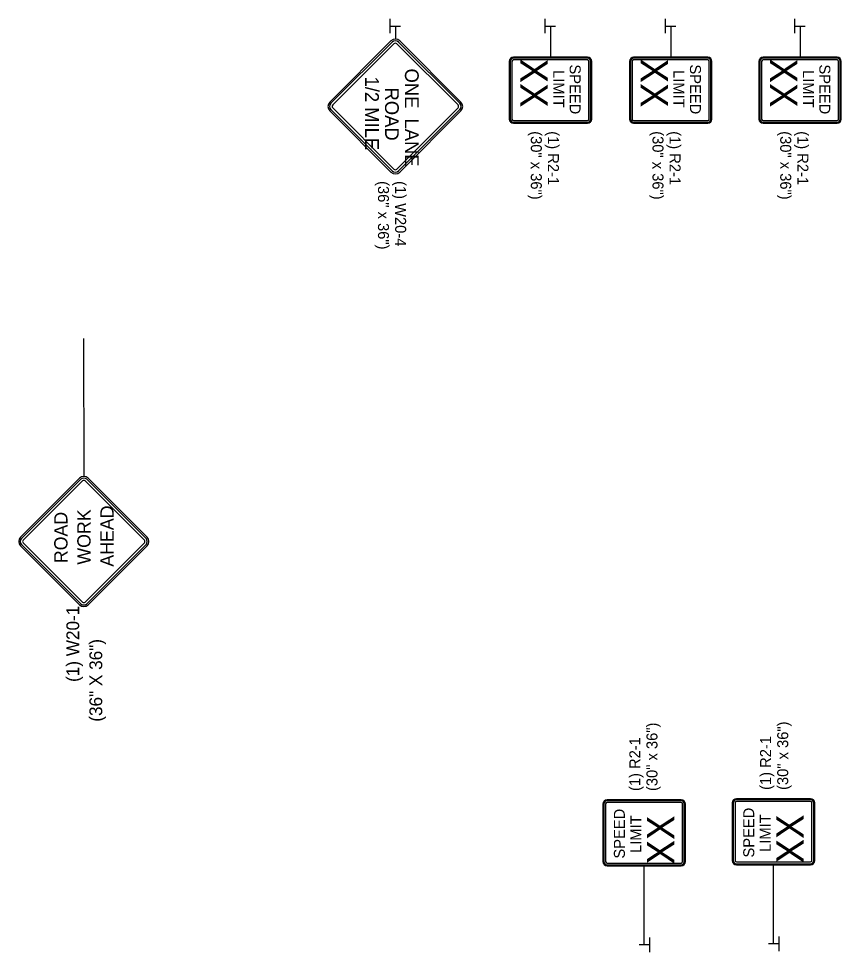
# Model space of a CAD drawing. Extents: x 1925873 to 1930787, y 596452 to 599617.
# Drawn here: x 1926733 to 1927182, y 598960 to 599469 of the extents above; entities that cross this region are included whole.
import ezdxf

# ---------------------------------------------------------------- set-up
doc = ezdxf.new("R2010")
doc.units = 0
for name, color, linetype in [('Default', 7, 'Continuous'), ('P_TC_Signs_Permanent', 7, 'Continuous'), ('P_TC_Signs_Temporary', 7, 'Continuous'), ('R_Border', 7, 'Continuous')]:
    doc.layers.add(name, color=color, linetype=linetype)

msp = doc.modelspace()

# ---------------------------------------------------------------- linework, layer by layer
at = {"layer": 'Default'}
for p, q in [((1926935.77, 599461.2), (1926935.77, 599469.2)), ((1927020.43, 599461.2), (1927020.43, 599469.2)), ((1927086.08, 599461.2), (1927086.08, 599469.2)), ((1927156.69, 599461.2), (1927156.69, 599469.2)), ((1926935.89, 599465.18), (1926941.35, 599465.18)), ((1927020.55, 599465.18), (1927026.01, 599465.18)), ((1927086.2, 599465.18), (1927091.66, 599465.18)), ((1927156.81, 599465.18), (1927162.27, 599465.18)), ((1927077.25, 598967.54), (1927077.25, 598959.53)), ((1927147.86, 598968.12), (1927147.86, 598960.11)), ((1927077.14, 598963.55), (1927071.67, 598963.55)), ((1927147.75, 598964.13), (1927142.28, 598964.13))]:
    msp.add_line(p, q, dxfattribs=at)
at = {"layer": 'P_TC_Signs_Permanent'}
for p, q in [((1927000.78, 599445.9), (1927000.78, 599414.4)), ((1927001.34, 599445.9), (1927001.34, 599414.4)), ((1927002.28, 599445.9), (1927002.28, 599414.4)), ((1927043.53, 599448.15), (1927003.03, 599448.15)), ((1927043.53, 599447.59), (1927003.03, 599447.59)), ((1927043.53, 599446.65), (1927003.03, 599446.65)), ((1927044.28, 599414.4), (1927044.28, 599445.9)), ((1927045.22, 599414.4), (1927045.22, 599445.9)), ((1927045.78, 599414.4), (1927045.78, 599445.9)), ((1927066.43, 599445.9), (1927066.43, 599414.4)), ((1927066.99, 599445.9), (1927066.99, 599414.4)), ((1927067.93, 599445.9), (1927067.93, 599414.4)), ((1927109.18, 599448.15), (1927068.68, 599448.15)), ((1927109.18, 599447.59), (1927068.68, 599447.59)), ((1927109.18, 599446.65), (1927068.68, 599446.65)), ((1927109.93, 599414.4), (1927109.93, 599445.9)), ((1927110.87, 599414.4), (1927110.87, 599445.9)), ((1927111.43, 599414.4), (1927111.43, 599445.9)), ((1927137.04, 599445.9), (1927137.04, 599414.4)), ((1927137.6, 599445.9), (1927137.6, 599414.4)), ((1927138.54, 599445.9), (1927138.54, 599414.4)), ((1927179.79, 599448.15), (1927139.29, 599448.15)), ((1927179.79, 599447.59), (1927139.29, 599447.59)), ((1927179.79, 599446.65), (1927139.29, 599446.65)), ((1927180.54, 599414.4), (1927180.54, 599445.9)), ((1927181.48, 599414.4), (1927181.48, 599445.9)), ((1927182.04, 599414.4), (1927182.04, 599445.9)), ((1927003.03, 599413.65), (1927043.53, 599413.65)), ((1927003.03, 599412.71), (1927043.53, 599412.71)), ((1927003.03, 599412.15), (1927043.53, 599412.15)), ((1927068.68, 599413.65), (1927109.18, 599413.65)), ((1927068.68, 599412.71), (1927109.18, 599412.71)), ((1927068.68, 599412.15), (1927109.18, 599412.15)), ((1927139.29, 599413.65), (1927179.79, 599413.65)), ((1927139.29, 599412.71), (1927179.79, 599412.71)), ((1927139.29, 599412.15), (1927179.79, 599412.15)), ((1927094.65, 599042.78), (1927054.15, 599042.78)), ((1927165.26, 599043.35), (1927124.76, 599043.35)), ((1927165.26, 599042.79), (1927124.76, 599042.79)), ((1927051.9, 599040.53), (1927051.9, 599009.03)), ((1927052.47, 599040.53), (1927052.47, 599009.03)), ((1927053.4, 599040.53), (1927053.4, 599009.03)), ((1927094.65, 599042.21), (1927054.15, 599042.21)), ((1927094.65, 599041.28), (1927054.15, 599041.28)), ((1927095.4, 599009.03), (1927095.4, 599040.53)), ((1927096.34, 599009.03), (1927096.34, 599040.53)), ((1927096.9, 599009.03), (1927096.9, 599040.53)), ((1927122.51, 599041.1), (1927122.51, 599009.6)), ((1927123.08, 599041.1), (1927123.08, 599009.6)), ((1927124.01, 599041.1), (1927124.01, 599009.6)), ((1927165.26, 599041.85), (1927124.76, 599041.85)), ((1927166.01, 599009.6), (1927166.01, 599041.1)), ((1927166.95, 599009.6), (1927166.95, 599041.1)), ((1927167.51, 599009.6), (1927167.51, 599041.1)), ((1927054.15, 599008.28), (1927094.65, 599008.28)), ((1927054.15, 599007.34), (1927094.65, 599007.34)), ((1927124.76, 599008.85), (1927165.26, 599008.85)), ((1927124.76, 599007.92), (1927165.26, 599007.92)), ((1927124.76, 599007.35), (1927165.26, 599007.35)), ((1927054.15, 599006.78), (1927094.65, 599006.78))]:
    msp.add_line(p, q, dxfattribs=at)
for centre, radius, start, end in [((1927003.03, 599445.9), 2.25, 90, 180), ((1927003.03, 599445.9), 1.69, 90, 180), ((1927003.03, 599445.9), 0.75, 90, 180), ((1927043.53, 599445.9), 2.25, 360, 90), ((1927043.53, 599445.9), 1.69, 360, 90), ((1927043.53, 599445.9), 0.75, 360, 90), ((1927068.68, 599445.9), 2.25, 90, 180), ((1927068.68, 599445.9), 1.69, 90, 180), ((1927068.68, 599445.9), 0.75, 90, 180), ((1927109.18, 599445.9), 2.25, 360, 90), ((1927109.18, 599445.9), 1.69, 360, 90), ((1927109.18, 599445.9), 0.75, 360, 90), ((1927139.29, 599445.9), 2.25, 90, 180), ((1927139.29, 599445.9), 1.69, 90, 180), ((1927139.29, 599445.9), 0.75, 90, 180), ((1927179.79, 599445.9), 2.25, 360, 90), ((1927179.79, 599445.9), 1.69, 360, 90), ((1927179.79, 599445.9), 0.75, 360, 90), ((1927003.03, 599414.4), 2.25, 180, 270), ((1927003.03, 599414.4), 1.69, 180, 270), ((1927003.03, 599414.4), 0.75, 180, 270), ((1927043.53, 599414.4), 2.25, 270, 360), ((1927043.53, 599414.4), 1.69, 270, 360), ((1927043.53, 599414.4), 0.75, 270, 360), ((1927068.68, 599414.4), 2.25, 180, 270), ((1927068.68, 599414.4), 1.69, 180, 270), ((1927068.68, 599414.4), 0.75, 180, 270), ((1927109.18, 599414.4), 2.25, 270, 360), ((1927109.18, 599414.4), 1.69, 270, 360), ((1927109.18, 599414.4), 0.75, 270, 360), ((1927139.29, 599414.4), 2.25, 180, 270), ((1927139.29, 599414.4), 1.69, 180, 270), ((1927139.29, 599414.4), 0.75, 180, 270), ((1927179.79, 599414.4), 2.25, 270, 360), ((1927179.79, 599414.4), 1.69, 270, 360), ((1927179.79, 599414.4), 0.75, 270, 360), ((1927054.15, 599040.53), 2.25, 90, 180), ((1927094.65, 599040.53), 2.25, 360, 90), ((1927124.76, 599041.1), 2.25, 90, 180), ((1927124.76, 599041.1), 1.69, 90, 180), ((1927165.26, 599041.1), 2.25, 360, 90), ((1927165.26, 599041.1), 1.69, 360, 90), ((1927054.15, 599040.53), 1.69, 90, 180), ((1927054.15, 599040.53), 0.75, 90, 180), ((1927094.65, 599040.53), 1.69, 360, 90), ((1927094.65, 599040.53), 0.75, 360, 90), ((1927124.76, 599041.1), 0.75, 90, 180), ((1927165.26, 599041.1), 0.75, 360, 90), ((1927054.15, 599009.03), 2.25, 180, 270), ((1927054.15, 599009.03), 1.69, 180, 270), ((1927054.15, 599009.03), 0.75, 180, 270), ((1927094.65, 599009.03), 2.25, 270, 360), ((1927094.65, 599009.03), 1.69, 270, 360), ((1927094.65, 599009.03), 0.75, 270, 360), ((1927124.76, 599009.6), 2.25, 180, 270), ((1927124.76, 599009.6), 1.69, 180, 270), ((1927124.76, 599009.6), 0.75, 180, 270), ((1927165.26, 599009.6), 2.25, 270, 360), ((1927165.26, 599009.6), 1.69, 270, 360), ((1927165.26, 599009.6), 0.75, 270, 360)]:
    msp.add_arc(centre, radius, start, end, dxfattribs=at)
at = {"layer": 'P_TC_Signs_Temporary'}
for p, q in [((1926902.82, 599423.67), (1926936.23, 599457.08)), ((1926903.48, 599423), (1926936.89, 599456.42)), ((1926940.34, 599456.42), (1926973.75, 599423)), ((1926941, 599457.08), (1926974.42, 599423.67)), ((1926904.41, 599422.08), (1926937.82, 599455.49)), ((1926939.41, 599455.49), (1926972.82, 599422.08)), ((1926937.82, 599387.07), (1926904.41, 599420.49)), ((1926972.82, 599420.49), (1926939.41, 599387.07)), ((1926936.23, 599385.48), (1926902.82, 599418.89)), ((1926936.89, 599386.15), (1926903.48, 599419.56)), ((1926973.75, 599419.56), (1926940.34, 599386.15)), ((1926974.42, 599418.89), (1926941, 599385.48)), ((1926766.28, 599218.4), (1926733.98, 599186.1)), ((1926766.92, 599217.76), (1926734.62, 599185.46)), ((1926767.82, 599216.86), (1926735.52, 599184.56)), ((1926801.65, 599184.56), (1926769.36, 599216.86)), ((1926802.55, 599185.46), (1926770.25, 599217.76)), ((1926803.19, 599186.1), (1926770.89, 599218.4)), ((1926733.98, 599181.49), (1926766.28, 599149.19)), ((1926734.62, 599182.13), (1926766.92, 599149.83)), ((1926735.52, 599183.03), (1926767.82, 599150.73)), ((1926769.36, 599150.73), (1926801.65, 599183.03)), ((1926770.25, 599149.83), (1926802.55, 599182.13)), ((1926770.89, 599149.19), (1926803.19, 599181.49))]:
    msp.add_line(p, q, dxfattribs=at)
for centre, radius, start, end in [((1926938.62, 599454.69), 3.37, 45, 135), ((1926938.62, 599454.69), 2.44, 45, 135), ((1926938.62, 599454.69), 1.12, 45, 135), ((1926905.21, 599421.28), 3.37, 135, 225), ((1926905.21, 599421.28), 2.44, 135, 225), ((1926905.21, 599421.28), 1.13, 135, 225), ((1926972.03, 599421.28), 1.13, 315, 45), ((1926972.03, 599421.28), 2.44, 315, 45), ((1926972.03, 599421.28), 3.37, 315, 45), ((1926938.62, 599387.87), 3.37, 225, 315), ((1926938.62, 599387.87), 2.44, 225, 315), ((1926938.62, 599387.87), 1.12, 225, 315), ((1926768.59, 599216.09), 3.26, 45, 135), ((1926768.59, 599216.09), 2.36, 45, 135), ((1926768.59, 599216.09), 1.09, 45, 135), ((1926736.29, 599183.79), 3.26, 135, 225), ((1926736.29, 599183.79), 2.36, 135, 225), ((1926800.88, 599183.79), 2.36, 315, 45), ((1926800.88, 599183.79), 3.26, 315, 45), ((1926736.29, 599183.79), 1.09, 135, 225), ((1926800.88, 599183.79), 1.09, 315, 45), ((1926768.59, 599151.5), 2.36, 225, 315), ((1926768.59, 599151.5), 1.09, 225, 315), ((1926768.59, 599151.5), 3.26, 225, 315)]:
    msp.add_arc(centre, radius, start, end, dxfattribs=at)
at = {"layer": 'R_Border'}
for p, q in [((1926938.62, 599465.18), (1926938.62, 599458.07)), ((1927023.28, 599465.18), (1927023.28, 599448.15)), ((1927088.93, 599465.18), (1927088.93, 599448.15)), ((1927159.54, 599465.18), (1927159.54, 599448.15)), ((1926768.47, 599294.58), (1926768.59, 599219.35)), ((1927145.01, 598964.13), (1927145.01, 599007.35)), ((1927074.4, 598963.55), (1927074.4, 599006.78))]:
    msp.add_line(p, q, dxfattribs=at)

# ---------------------------------------------------------------- texts
at = {"layer": 'Default'}
for s, p in [('(1) W20-1', (1926766.06, 599107.13)), ('(36" X 36")', (1926778.63, 599085.42))]:
    msp.add_text(s, height=7, rotation=90, dxfattribs=at).set_placement(p)
at = {"layer": 'P_TC_Signs_Permanent'}
for s, height, rotation, p in [('XX', 15, 270, (1927006.78, 599447.45)), ('XX', 15, 270, (1927072.43, 599447.45)), ('XX', 15, 270, (1927143.04, 599447.45)), ('LIMIT', 6, 270, (1927024.78, 599441.13)), ('SPEED', 6, 270, (1927033.78, 599444.22)), ('LIMIT', 6, 270, (1927090.43, 599441.13)), ('SPEED', 6, 270, (1927099.43, 599444.22)), ('LIMIT', 6, 270, (1927161.04, 599441.13)), ('SPEED', 6, 270, (1927170.04, 599444.22)), ('SPEED', 6, 90, (1927134.51, 599011.28)), ('SPEED', 6, 90, (1927063.9, 599010.71)), ('LIMIT', 6, 90, (1927072.9, 599013.8)), ('XX', 15, 90, (1927090.9, 599007.48)), ('LIMIT', 6, 90, (1927143.51, 599014.37)), ('XX', 15, 90, (1927161.51, 599008.05))]:
    msp.add_text(s, height=height, rotation=rotation, dxfattribs=at).set_placement(p)
at = {"layer": 'P_TC_Signs_Temporary'}
for s, height, rotation, p in [('ONE  LANE', 7.5, 270, (1926943.87, 599441.98)), ('1/2 MILE', 7.5, 270, (1926922.12, 599437.6)), ('ROAD', 7.5, 270, (1926932.99, 599431.59)), ('WORK', 7.25, 90, (1926772.27, 599171.16)), (' AHEAD ', 7.25, 90, (1926784.86, 599167.36)), (' ROAD ', 7.25, 90, (1926759.68, 599169.27))]:
    msp.add_text(s, height=height, rotation=rotation, dxfattribs=at).set_placement(p)
at = {"layer": 'R_Border'}
for s, height, rotation, p in [('(30" x 36")', 5.9996, 270, (1927012.56, 599407.77)), ('(1) R2-1', 6, 270, (1927021.92, 599407.77)), ('(30" x 36")', 5.9996, 270, (1927078.97, 599407.77)), ('(1) R2-1', 6, 270, (1927088.33, 599407.77)), ('(30" x 36")', 5.9996, 270, (1927148.69, 599407.77)), ('(1) R2-1', 6, 270, (1927158.05, 599407.77)), ('(36" x 36")', 5.9996, 270, (1926929.14, 599380.55)), ('(1) W20-4', 6, 270, (1926938.51, 599380.55)), ('(30" x 36")', 5.9996, 90, (1927081.69, 599047.58)), ('(30" x 36")', 5.9996, 90, (1927153.05, 599048.18)), ('(1) R2-1', 6, 90, (1927072.33, 599047.58)), ('(1) R2-1', 6, 90, (1927143.68, 599048.18))]:
    msp.add_text(s, height=height, rotation=rotation, dxfattribs=at).set_placement(p)

doc.saveas('drawing.dxf')
